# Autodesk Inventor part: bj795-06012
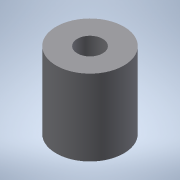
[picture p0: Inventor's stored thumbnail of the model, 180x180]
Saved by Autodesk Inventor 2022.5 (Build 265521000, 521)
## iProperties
Created: 2016-12
Part Number: bj795-06012
Material: 一般
Document SubType Name: Modeling
Designer: imaocorp
Density: 1 g/cm^3
Appearance: 既定
Author: imaocorp
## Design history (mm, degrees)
node "bj795-06012.x_t1"
node "bj795-06012"
node "Base1"
